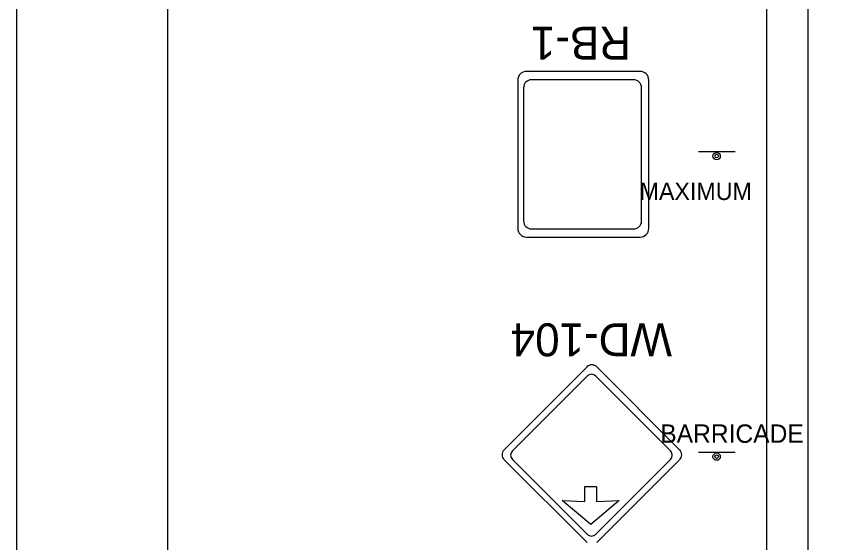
# Model space of a CAD drawing. Extents: x 797 to 1013, y 120 to 399.
# Drawn here: x 797.2 to 851.4, y 330.8 to 365.6 of the extents above; entities that cross this region are included whole.
import ezdxf

# ---------------------------------------------------------------- set-up
doc = ezdxf.new("R2010")
doc.units = 0
for name, color, linetype in [('Level 10', 7, 'Continuous'), ('Level 44', 7, 'Continuous'), ('Level 60', 7, 'Continuous')]:
    doc.layers.add(name, color=color, linetype=linetype)

msp = doc.modelspace()

# ---------------------------------------------------------------- linework, layer by layer
at = {"layer": 'Level 10'}
for p, q in [((846.784, 383.976), (846.784, 135.758)), ((849.539, 383.976), (849.539, 135.758))]:
    msp.add_line(p, q, dxfattribs=at)
at = {"layer": 'Level 44'}
for p, q in [((838.428, 361.951), (830.916, 361.951)), ((831.049, 361.709), (831.049, 361.709)), ((830.337, 361.372), (830.337, 361.369)), ((830.337, 361.369), (830.337, 351.578)), ((838.005, 361.396), (831.245, 361.396)), ((839.009, 351.578), (839.009, 361.369)), ((830.724, 360.875), (830.724, 360.873)), ((830.724, 360.873), (830.724, 352.061)), ((838.528, 352.061), (838.528, 360.873)), ((844.711, 356.623), (842.287, 356.623)), ((831.245, 351.539), (838.005, 351.539)), ((830.916, 350.998), (838.428, 350.998)), ((829.428, 336.934), (834.917, 342.421)), ((835.566, 342.421), (841.046, 336.934)), ((834.917, 341.811), (829.978, 336.874)), ((840.435, 336.874), (835.501, 341.811)), ((829.433, 336.934), (829.428, 336.934)), ((844.711, 336.757), (842.287, 336.757)), ((834.917, 330.803), (829.428, 336.283)), ((829.978, 336.288), (834.917, 331.355)), ((835.501, 331.355), (840.435, 336.288)), ((841.046, 336.283), (835.566, 330.803)), ((834.781, 334.518), (835.532, 334.518)), ((834.781, 333.511), (834.781, 334.518)), ((835.537, 334.518), (835.537, 333.511)), ((835.159, 332.003), (833.273, 333.592)), ((833.273, 333.592), (834.781, 333.511)), ((837.045, 333.592), (835.159, 332.003)), ((835.537, 333.511), (837.045, 333.592))]:
    msp.add_line(p, q, dxfattribs=at)
for centre, radius in [((843.495, 356.352), 0.242), ((843.495, 356.352), 0.121), ((843.495, 336.485), 0.242), ((843.495, 336.485), 0.121)]:
    msp.add_circle(centre, radius, dxfattribs=at)
for centre, radius, start, end in [((830.917, 361.371), 0.58, 90, 180), ((838.428, 361.371), 0.58, 0, 90), ((831.245, 360.875), 0.522, 90, 180), ((838.005, 360.875), 0.522, 0, 90), ((831.245, 352.062), 0.522, 180, 270), ((838.005, 352.062), 0.522, 270, 0), ((830.917, 351.579), 0.58, 180, 270), ((838.428, 351.579), 0.58, 270, 0), ((835.24, 342.093), 0.459, 45, 135), ((835.208, 341.517), 0.413, 45, 135), ((829.756, 336.61), 0.459, 135, 225), ((830.272, 336.582), 0.413, 135, 225), ((840.143, 336.582), 0.413, 315, 45), ((840.724, 336.61), 0.459, 315, 45), ((835.208, 331.646), 0.413, 225, 315)]:
    msp.add_arc(centre, radius, start, end, dxfattribs=at)
at = {"layer": 'Level 60'}
for points in [[(1013.16, 399.381), (797.16, 399.381), (797.16, 120.381), (1013.16, 120.381)], [(994.034, 388.572), (807.16, 388.572), (807.16, 131.19), (994.034, 131.19)]]:
    msp.add_lwpolyline(points, close=True, dxfattribs=at)

# ---------------------------------------------------------------- texts
at = {"layer": 'Level 10'}
for s, p in [('RB-1', (837.833, 364.901)), ('WD-104', (840.541, 345.298))]:
    msp.add_text(s, height=2.1769, rotation=180, dxfattribs=at).set_placement(p)
at = {"layer": 'Level 44'}
for s, height, p in [('MAXIMUM', 1.149, (838.397, 353.452)), ('BARRICADE', 1.2169, (839.765, 337.398))]:
    msp.add_text(s, height=height, rotation=0, dxfattribs=at).set_placement(p)

doc.saveas('drawing.dxf')
